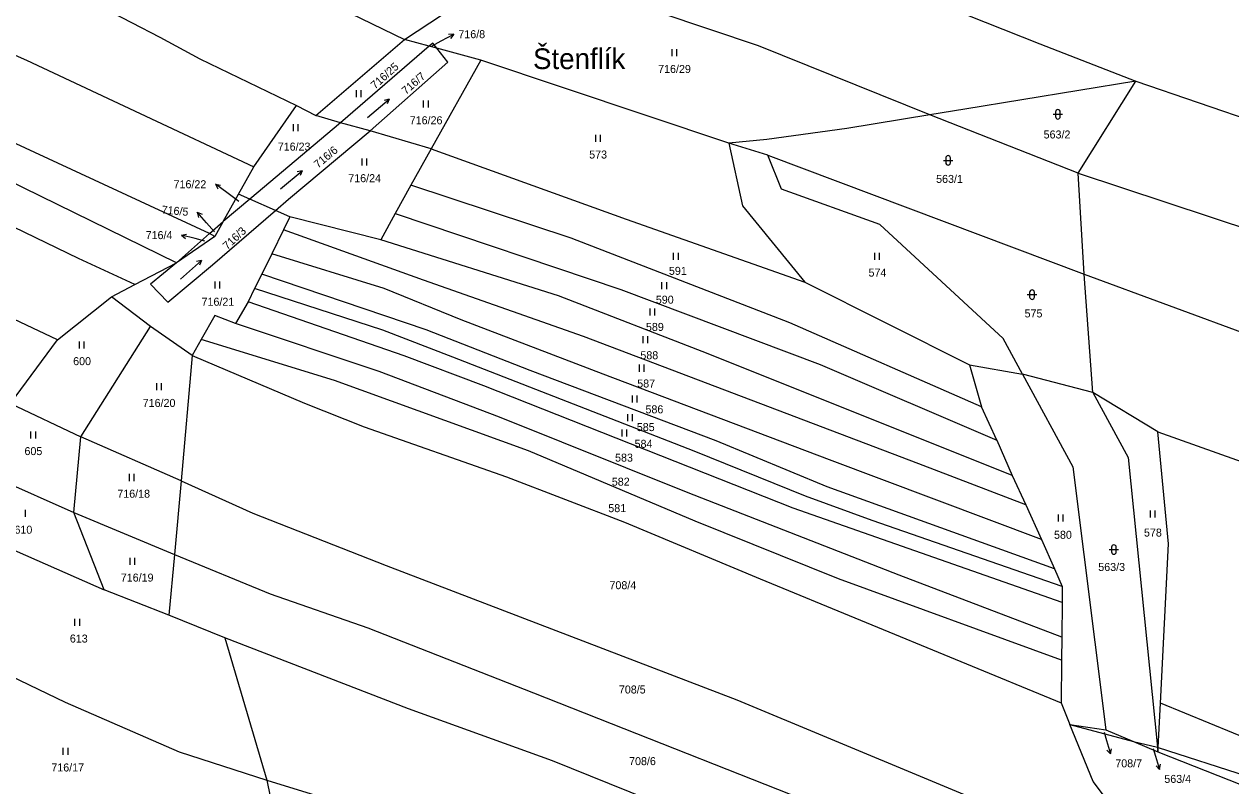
# Model space of a CAD drawing. Extents: x -751333 to -746055, y -1133395 to -1129777.
# Drawn here: x -748441 to -748184.6, y -1131157.3 to -1130995.4 of the extents above; entities that cross this region are included whole.
import ezdxf

# ---------------------------------------------------------------- set-up
doc = ezdxf.new("R2010")
doc.units = 0
for name, color, linetype in [('Hranice parcel', 7, 'Continuous'), ('Parcelní čísla', 7, 'Continuous'), ('Pop  PČ popisy', 7, 'Continuous'), ('Značky kultur', 7, 'Continuous')]:
    doc.layers.add(name, color=color, linetype=linetype)

msp = doc.modelspace()

# ---------------------------------------------------------------- linework, layer by layer
at = {"layer": 'Hranice parcel'}
for p, q in [((-748360.19, -1130998.63), (-748338.46, -1130984.21)), ((-748379, -1131014.81), (-748360.19, -1130998.63)), ((-748354.9, -1131000.06), (-748360.19, -1130998.63)), ((-748354.9, -1131000.06), (-748373.77, -1131016.38)), ((-748353.27, -1131000.5), (-748354.9, -1131000.06)), ((-748343.93, -1131003.03), (-748353.27, -1131000.5)), ((-748343.93, -1131003.03), (-748354.54, -1131021.9)), ((-748291.24, -1131020.69), (-748343.93, -1131003.03)), ((-748217.06, -1131027.07), (-748204.79, -1131007.48)), ((-748392.16, -1131025.73), (-748383.15, -1131012.7)), ((-748383.15, -1131012.7), (-748379, -1131014.81)), ((-748217.06, -1131027.07), (-748248.56, -1131014.62)), ((-748373.77, -1131016.38), (-748393.03, -1131032.57)), ((-748373.77, -1131016.38), (-748379, -1131014.81)), ((-748367.47, -1131018.07), (-748373.77, -1131016.38)), ((-748354.54, -1131021.9), (-748367.47, -1131018.07)), ((-748354.54, -1131021.9), (-748358.83, -1131029.64)), ((-748283.01, -1131023.21), (-748291.24, -1131020.69)), ((-748283.01, -1131023.21), (-748215.75, -1131048.5)), ((-748395.42, -1131031.51), (-748392.16, -1131025.73)), ((-748215.75, -1131048.5), (-748217.06, -1131027.07)), ((-748358.83, -1131029.64), (-748362.13, -1131035.6)), ((-748398.67, -1131037.3), (-748395.42, -1131031.51)), ((-748393.03, -1131032.57), (-748398.67, -1131037.3)), ((-748393.03, -1131032.57), (-748395.42, -1131031.51)), ((-748387.58, -1131034.98), (-748393.03, -1131032.57)), ((-748384.5, -1131036.34), (-748387.58, -1131034.98)), ((-748401.59, -1131039.86), (-748398.67, -1131037.3)), ((-748398.67, -1131037.3), (-748400.45, -1131040.5)), ((-748384.5, -1131036.34), (-748385.87, -1131039.12)), ((-748365.22, -1131041.21), (-748384.5, -1131036.34)), ((-748362.13, -1131035.6), (-748365.22, -1131041.21)), ((-748408.58, -1131046.09), (-748401.59, -1131039.86)), ((-748400.45, -1131040.5), (-748401.59, -1131039.86)), ((-748385.87, -1131039.12), (-748388.38, -1131044.22)), ((-748400.45, -1131040.5), (-748408.58, -1131046.09)), ((-748388.38, -1131044.22), (-748390.49, -1131048.5)), ((-748417.45, -1131050.74), (-748408.58, -1131046.09)), ((-748390.49, -1131048.5), (-748392.02, -1131051.59)), ((-748275.09, -1131050.22), (-748240.13, -1131067.81)), ((-748213.94, -1131073.65), (-748215.75, -1131048.5)), ((-748422.44, -1131053.36), (-748417.45, -1131050.74)), ((-748392.02, -1131051.59), (-748393.4, -1131054.38)), ((-748433.86, -1131062.5), (-748422.44, -1131053.36)), ((-748414.11, -1131059.62), (-748422.44, -1131053.36)), ((-748393.4, -1131054.38), (-748396.09, -1131058.99)), ((-748428.96, -1131083.09), (-748414.11, -1131059.62)), ((-748405.3, -1131065.79), (-748414.11, -1131059.62)), ((-748443.88, -1131076.03), (-748433.86, -1131062.5)), ((-748403.37, -1131062.41), (-748405.3, -1131065.79)), ((-748405.3, -1131065.79), (-748407.59, -1131092.49)), ((-748240.13, -1131067.81), (-748237.57, -1131076.74)), ((-748240.13, -1131067.81), (-748228.85, -1131069.78)), ((-748213.94, -1131073.65), (-748228.85, -1131069.78)), ((-748443.88, -1131076.03), (-748428.96, -1131083.09)), ((-748200.15, -1131082.03), (-748213.94, -1131073.65)), ((-748234.3, -1131083.82), (-748237.57, -1131076.74)), ((-748430.39, -1131099.21), (-748428.96, -1131083.09)), ((-748407.59, -1131092.49), (-748428.96, -1131083.09)), ((-748234.3, -1131083.82), (-748231.06, -1131091.34)), ((-748451.45, -1131089.82), (-748430.39, -1131099.21)), ((-748231.06, -1131091.34), (-748228.17, -1131097.58)), ((-748407.59, -1131092.49), (-748409.03, -1131108.09)), ((-748430.39, -1131099.21), (-748409.03, -1131108.09)), ((-748424, -1131115.63), (-748430.39, -1131099.21)), ((-748228.17, -1131097.58), (-748224.84, -1131104.96)), ((-748457.53, -1131100.91), (-748424, -1131115.63)), ((-748224.84, -1131104.96), (-748222.1, -1131111.15)), ((-748409.03, -1131108.09), (-748410.22, -1131121.04)), ((-748222.1, -1131111.15), (-748220.43, -1131114.9)), ((-748410.22, -1131121.04), (-748424, -1131115.63)), ((-748220.43, -1131114.9), (-748220.47, -1131118.31)), ((-748220.47, -1131118.31), (-748220.53, -1131125.72)), ((-748398.34, -1131125.81), (-748410.22, -1131121.04)), ((-748398.34, -1131125.81), (-748389.42, -1131156.09)), ((-748220.53, -1131125.72), (-748220.57, -1131130.55)), ((-748220.57, -1131130.55), (-748220.64, -1131139.62)), ((-748220.64, -1131139.62), (-748218.82, -1131144.23)), ((-748200.06, -1131149.14), (-748199.59, -1131139.75)), ((-748106.65, -1131177.93), (-748199.59, -1131139.75)), ((-748218.82, -1131144.23), (-748205.28, -1131147.89)), ((-748218.82, -1131144.23), (-748211.14, -1131145.42)), ((-748211.14, -1131145.42), (-748205.28, -1131147.89)), ((-748205.28, -1131147.89), (-748200.2, -1131149.11)), ((-748205.28, -1131147.89), (-748200.11, -1131150.07)), ((-748200.2, -1131149.11), (-748200.11, -1131150.07)), ((-748200.11, -1131150.07), (-748200.06, -1131149.14)), ((-748389.42, -1131156.09), (-748383.08, -1131187.24))]:
    msp.add_line(p, q, dxfattribs=at)
for points in [[(-748485.95, -1130936.62), (-748455.56, -1130954.14), (-748433.55, -1130964.26), (-748406.22, -1130976.23), (-748360.19, -1130998.63)], [(-748512.7, -1130944.65), (-748464.62, -1130973.2), (-748424.22, -1130991.94), (-748412.15, -1130998.16), (-748403.69, -1131002.73), (-748383.15, -1131012.7)], [(-748537.89, -1130953.74), (-748526.55, -1130964.01), (-748475.44, -1130987.44), (-748440.48, -1131003.02), (-748392.16, -1131025.73)], [(-748401.59, -1131039.86), (-748482.79, -1131002.25), (-748525.81, -1130981.98), (-748560.43, -1130965.34), (-748569.8, -1130959.62)], [(-748408.58, -1131046.09), (-748444.76, -1131028.43), (-748487.86, -1131009.7), (-748519.33, -1130996.05), (-748562.72, -1130976.46), (-748581.99, -1130964.07)], [(-748417.45, -1131050.74), (-748429.46, -1131045.22), (-748443.17, -1131038.57), (-748447.76, -1131036), (-748521.8, -1131003.51), (-748563.34, -1130984.99), (-748581.03, -1130975.42), (-748590.75, -1130967.27)], [(-748298.99, -1130970.22), (-748225.2, -1130999.57), (-748204.79, -1131007.48)], [(-748433.86, -1131062.5), (-748469.72, -1131045.54), (-748503.59, -1131029.98), (-748535.57, -1131015.06), (-748590.35, -1130992.22), (-748617.7, -1130976.74)], [(-748248.56, -1131014.62), (-748284.95, -1131000.02), (-748316.44, -1130989.36), (-748338.46, -1130984.21)], [(-748367.47, -1131018.07), (-748350.94, -1131003.46), (-748353.27, -1131000.5)], [(-748353.27, -1131000.5), (-748354.14, -1130999.4), (-748354.9, -1131000.06)], [(-748204.79, -1131007.48), (-748241.16, -1131013.45), (-748248.56, -1131014.62)], [(-748204.79, -1131007.48), (-748178.35, -1131016.55), (-748147.39, -1131029.12), (-748128.96, -1131036.36), (-748096.79, -1131049.01), (-748070.74, -1131060.67), (-748045.79, -1131075.87)], [(-748248.56, -1131014.62), (-748266.19, -1131017.56), (-748283.2, -1131019.93), (-748291.24, -1131020.69)], [(-748387.58, -1131034.98), (-748384.84, -1131032.61), (-748367.47, -1131018.07)], [(-748354.54, -1131021.9), (-748313.1, -1131036.82), (-748275.09, -1131050.22)], [(-748291.24, -1131020.69), (-748288.34, -1131033.98), (-748275.09, -1131050.22)], [(-748228.85, -1131069.78), (-748232.97, -1131062.2), (-748259.19, -1131037.98), (-748280.09, -1131030.45), (-748283.01, -1131023.21)], [(-748217.06, -1131027.07), (-748179.59, -1131039.45), (-748106.1, -1131070.73), (-748056.24, -1131094.99)], [(-748237.57, -1131076.74), (-748278.3, -1131058.9), (-748324.79, -1131040.88), (-748358.83, -1131029.64)], [(-748408.58, -1131046.09), (-748414.17, -1131050.66), (-748410.47, -1131054.51), (-748400.96, -1131046.55), (-748387.58, -1131034.98)], [(-748362.13, -1131035.6), (-748314.24, -1131051.8), (-748271.86, -1131067.7), (-748234.3, -1131083.82)], [(-748228.17, -1131097.58), (-748250.9, -1131088.82), (-748322.13, -1131061.79), (-748356.17, -1131049.78), (-748385.87, -1131039.12)], [(-748231.06, -1131091.34), (-748295.64, -1131065.48), (-748327.49, -1131053.12), (-748365.22, -1131041.21)], [(-748224.84, -1131104.96), (-748269.91, -1131088.03), (-748317.94, -1131069.78), (-748348.15, -1131058.2), (-748364.47, -1131051.6), (-748388.38, -1131044.22)], [(-748222.1, -1131111.15), (-748270.35, -1131093.73), (-748293.98, -1131083.95), (-748333.47, -1131069.02), (-748355.58, -1131060.36), (-748390.49, -1131048.5)], [(-748215.75, -1131048.5), (-748179.65, -1131061.85), (-748147.12, -1131075.88), (-748110.29, -1131091.1), (-748067.39, -1131114.45)], [(-748220.43, -1131114.9), (-748260.8, -1131100.91), (-748275, -1131095.72), (-748298.6, -1131086.14), (-748349.88, -1131066.18), (-748364.77, -1131060.43), (-748392.02, -1131051.59)], [(-748220.47, -1131118.31), (-748277.63, -1131098.3), (-748343.3, -1131072.28), (-748360.23, -1131065.88), (-748393.4, -1131054.38)], [(-748396.09, -1131058.99), (-748400.45, -1131057.32), (-748403.37, -1131062.41)], [(-748220.53, -1131125.72), (-748255.06, -1131112.5), (-748299.92, -1131094.99), (-748339.97, -1131078.96), (-748365.59, -1131069.23), (-748396.09, -1131058.99)], [(-748220.57, -1131130.55), (-748267.98, -1131113.3), (-748298.42, -1131101.04), (-748333.85, -1131086.07), (-748375.02, -1131071.11), (-748403.37, -1131062.41)], [(-748405.3, -1131065.79), (-748381.45, -1131075.94), (-748368.77, -1131080.97), (-748338.48, -1131091.58), (-748313.45, -1131101.22), (-748284.62, -1131113.32), (-748220.64, -1131139.62)], [(-748228.85, -1131069.78), (-748218.16, -1131089.46), (-748211.14, -1131145.42)], [(-748213.94, -1131073.65), (-748206.41, -1131087.48), (-748200.2, -1131149.11)], [(-748200.15, -1131082.03), (-748154.2, -1131098.38), (-748119.78, -1131111.85), (-748078.05, -1131132.75)], [(-748199.59, -1131139.75), (-748197.87, -1131105.84), (-748200.15, -1131082.03)], [(-748407.59, -1131092.49), (-748392.37, -1131099.36), (-748364.1, -1131110.45), (-748289.57, -1131139.04), (-748228.18, -1131164.59), (-748198.94, -1131176.25)], [(-748409.03, -1131108.09), (-748388.71, -1131116.46), (-748367.99, -1131123.74), (-748332.74, -1131137.52), (-748261.74, -1131165.6), (-748191.48, -1131193.81)], [(-748469.85, -1131122.34), (-748447.76, -1131132.08), (-748432.29, -1131139.48), (-748408.02, -1131150.06), (-748389.42, -1131156.09)], [(-748194.07, -1131207.17), (-748250.95, -1131183.36), (-748328.73, -1131151.99), (-748359.3, -1131140.91), (-748398.34, -1131125.81)], [(-748198.94, -1131176.25), (-748213.86, -1131156.39), (-748218.82, -1131144.23)], [(-748200.11, -1131150.07), (-748142.12, -1131172.94), (-748114.48, -1131184.54)], [(-748200.06, -1131149.14), (-748181.16, -1131155.26), (-748136.15, -1131172.02), (-748112.26, -1131184.92)], [(-748389.42, -1131156.09), (-748377.21, -1131159.87), (-748336.88, -1131177.2), (-748290.63, -1131196.06), (-748226.11, -1131222.02), (-748199.48, -1131232.89), (-748187.31, -1131238.43)]]:
    msp.add_lwpolyline(points, dxfattribs=at)
at = {"layer": 'Pop  PČ popisy'}
for p, q in [((-748354.3, -1130999.96), (-748352.37, -1130998.93)), ((-748352.37, -1130998.93), (-748349.72, -1130997.521)), ((-748349.72, -1130997.521), (-748350.84, -1130997.549)), ((-748349.72, -1130997.521), (-748350.369, -1130998.433)), ((-748397.94, -1131031.2), (-748400.337, -1131029.394)), ((-748400.337, -1131029.394), (-748399.236, -1131029.597)), ((-748400.337, -1131029.394), (-748399.838, -1131030.397)), ((-748395.38, -1131033.11), (-748397.94, -1131031.2)), ((-748402.22, -1131037.64), (-748404.189, -1131035.375)), ((-748404.189, -1131035.375), (-748403.154, -1131035.802)), ((-748404.189, -1131035.375), (-748403.91, -1131036.459)), ((-748400.57, -1131039.56), (-748402.22, -1131037.64)), ((-748407.572, -1131040.234), (-748406.479, -1131039.99)), ((-748404.66, -1131040.96), (-748407.572, -1131040.234)), ((-748407.572, -1131040.234), (-748406.721, -1131040.962)), ((-748402.56, -1131041.48), (-748404.66, -1131040.96)), ((-748211.51, -1131145.87), (-748211, -1131147.64)), ((-748211, -1131147.64), (-748210.173, -1131150.525)), ((-748210.173, -1131150.525), (-748210.93, -1131149.7)), ((-748210.173, -1131150.525), (-748209.968, -1131149.424)), ((-748201.1, -1131149.36), (-748200.62, -1131150.96)), ((-748200.62, -1131150.96), (-748199.743, -1131153.83)), ((-748199.743, -1131153.83), (-748200.514, -1131153.019)), ((-748199.743, -1131153.83), (-748199.557, -1131152.726))]:
    msp.add_line(p, q, dxfattribs=at)
at = {"layer": 'Značky kultur'}
for p, q in [((-748303.341, -1131002.2), (-748303.341, -1131000.7)), ((-748302.34, -1131002.2), (-748302.34, -1131000.7)), ((-748370.361, -1131010.9), (-748370.361, -1131009.4)), ((-748369.36, -1131010.9), (-748369.36, -1131009.4)), ((-748368.019, -1131015.194), (-748363.423, -1131011.337)), ((-748363.423, -1131011.337), (-748364.494, -1131011.581)), ((-748363.423, -1131011.337), (-748363.849, -1131012.349)), ((-748356.111, -1131013.11), (-748356.111, -1131011.61)), ((-748355.11, -1131013.11), (-748355.11, -1131011.61)), ((-748222.371, -1131014.541), (-748220.369, -1131014.541)), ((-748221.871, -1131014.041), (-748221.871, -1131015.042)), ((-748220.869, -1131015.042), (-748220.869, -1131014.041)), ((-748383.771, -1131018.16), (-748383.771, -1131016.66)), ((-748382.77, -1131018.16), (-748382.77, -1131016.66)), ((-748319.541, -1131020.39), (-748319.541, -1131018.89)), ((-748318.54, -1131020.39), (-748318.54, -1131018.89)), ((-748369.171, -1131025.42), (-748369.171, -1131023.92)), ((-748368.17, -1131025.42), (-748368.17, -1131023.92)), ((-748245.691, -1131024.331), (-748243.689, -1131024.331)), ((-748245.191, -1131023.831), (-748245.191, -1131024.832)), ((-748244.189, -1131024.832), (-748244.189, -1131023.831)), ((-748386.509, -1131030.384), (-748381.913, -1131026.527)), ((-748381.913, -1131026.527), (-748382.984, -1131026.771)), ((-748381.913, -1131026.527), (-748382.339, -1131027.539)), ((-748302.991, -1131045.5), (-748302.991, -1131044)), ((-748301.99, -1131045.5), (-748301.99, -1131044)), ((-748260.271, -1131045.49), (-748260.271, -1131043.99)), ((-748259.27, -1131045.49), (-748259.27, -1131043.99)), ((-748407.781, -1131049.602), (-748403.322, -1131045.588)), ((-748403.322, -1131045.588), (-748404.384, -1131045.869)), ((-748403.322, -1131045.588), (-748403.713, -1131046.614)), ((-748400.401, -1131051.56), (-748400.401, -1131050.06)), ((-748399.4, -1131051.56), (-748399.4, -1131050.06)), ((-748305.471, -1131051.74), (-748305.471, -1131050.24)), ((-748304.47, -1131051.74), (-748304.47, -1131050.24)), ((-748227.861, -1131052.881), (-748225.859, -1131052.881)), ((-748227.361, -1131052.381), (-748227.361, -1131053.382)), ((-748226.359, -1131053.382), (-748226.359, -1131052.381)), ((-748307.991, -1131057.29), (-748307.991, -1131055.79)), ((-748306.99, -1131057.29), (-748306.99, -1131055.79)), ((-748429.211, -1131064.32), (-748429.211, -1131062.82)), ((-748428.21, -1131064.32), (-748428.21, -1131062.82)), ((-748309.471, -1131063.2), (-748309.471, -1131061.7)), ((-748308.47, -1131063.2), (-748308.47, -1131061.7)), ((-748310.281, -1131069.26), (-748310.281, -1131067.76)), ((-748309.28, -1131069.26), (-748309.28, -1131067.76)), ((-748412.821, -1131073.2), (-748412.821, -1131071.7)), ((-748411.82, -1131073.2), (-748411.82, -1131071.7)), ((-748311.711, -1131075.79), (-748311.711, -1131074.29)), ((-748310.71, -1131075.79), (-748310.71, -1131074.29)), ((-748312.701, -1131079.81), (-748312.701, -1131078.31)), ((-748311.7, -1131079.81), (-748311.7, -1131078.31)), ((-748439.531, -1131083.44), (-748439.531, -1131081.94)), ((-748438.53, -1131083.44), (-748438.53, -1131081.94)), ((-748313.961, -1131083.06), (-748313.961, -1131081.56)), ((-748312.96, -1131083.06), (-748312.96, -1131081.56)), ((-748418.591, -1131092.5), (-748418.591, -1131091)), ((-748417.59, -1131092.5), (-748417.59, -1131091)), ((-748440.72, -1131100.14), (-748440.72, -1131098.64)), ((-748201.671, -1131100.28), (-748201.671, -1131098.78)), ((-748200.67, -1131100.28), (-748200.67, -1131098.78)), ((-748221.221, -1131101.14), (-748221.221, -1131099.64)), ((-748220.22, -1131101.14), (-748220.22, -1131099.64)), ((-748209.971, -1131106.571), (-748209.971, -1131107.572)), ((-748208.969, -1131107.572), (-748208.969, -1131106.571)), ((-748418.451, -1131110.34), (-748418.451, -1131108.84)), ((-748417.45, -1131110.34), (-748417.45, -1131108.84)), ((-748210.471, -1131107.071), (-748208.469, -1131107.071)), ((-748430.181, -1131123.29), (-748430.181, -1131121.79)), ((-748429.18, -1131123.29), (-748429.18, -1131121.79)), ((-748432.661, -1131150.7), (-748432.661, -1131149.2)), ((-748431.66, -1131150.7), (-748431.66, -1131149.2))]:
    msp.add_line(p, q, dxfattribs=at)
for centre, start, end in [((-748221.37, -1131014.041), 0, 180), ((-748221.37, -1131015.041), 180, 359.98789), ((-748244.69, -1131023.831), 0, 180), ((-748244.69, -1131024.831), 180, 359.98789), ((-748226.86, -1131052.381), 0, 180), ((-748226.86, -1131053.381), 180, 359.98789), ((-748209.47, -1131106.571), 0, 180), ((-748209.47, -1131107.571), 180, 359.98789)]:
    msp.add_arc(centre, 0.5, start, end, dxfattribs=at)

# ---------------------------------------------------------------- texts
at = {"layer": 'Parcelní čísla'}
for s, p in [('716/8', (-748348.73, -1130998.36)), ('716/29', (-748306.29, -1131005.75)), ('716/26', (-748359.06, -1131016.66)), ('563/2', (-748224.39, -1131019.68)), ('716/23', (-748387.1, -1131022.26)), ('573', (-748320.94, -1131023.94)), ('716/24', (-748372.12, -1131028.97)), ('563/1', (-748247.23, -1131029.13)), ('716/22', (-748409.235, -1131030.26)), ('716/4', (-748415.167, -1131041.08)), ('591', (-748304, -1131048.67)), ('574', (-748261.59, -1131049.04)), ('590', (-748306.78, -1131054.8)), ('716/21', (-748403.29, -1131055.24)), ('575', (-748228.44, -1131057.72)), ('589', (-748308.88, -1131060.59)), ('588', (-748310.06, -1131066.61)), ('600', (-748430.57, -1131067.87)), ('587', (-748310.73, -1131072.62)), ('716/20', (-748415.79, -1131076.75)), ('586', (-748308.98, -1131078.11)), ('585', (-748310.82, -1131081.89)), ('584', (-748311.29, -1131085.44)), ('605', (-748440.91, -1131086.99)), ('583', (-748315.44, -1131088.38)), ('582', (-748316.13, -1131093.49)), ('716/18', (-748421.19, -1131096.05)), ('581', (-748316.87, -1131099.12)), ('610', (-748443.04, -1131103.7)), ('580', (-748222.18, -1131104.78)), ('578', (-748203.07, -1131104.31)), ('563/3', (-748212.78, -1131111.62)), ('716/19', (-748420.45, -1131113.88)), ('708/4', (-748316.63, -1131115.5)), ('613', (-748431.27, -1131126.84)), ('708/5', (-748314.63, -1131137.67)), ('716/17', (-748435.2, -1131154.25)), ('708/6', (-748312.46, -1131152.9)), ('708/7', (-748209.16, -1131153.368)), ('563/4', (-748198.75, -1131156.678))]:
    msp.add_text(s, height=1.7, dxfattribs=at).set_placement(p)
for s, rotation, p in [('716/25', 42, (-748366.411, -1131009.301)), ('716/7', 41, (-748359.862, -1131010.451)), ('716/6', 40, (-748378.533, -1131026.101)), ('716/5', 355, (-748411.826, -1131035.641)), ('716/3', 43, (-748397.81, -1131043.431))]:
    msp.add_text(s, height=1.7, rotation=rotation, dxfattribs=at).set_placement(p)
at = {"layer": 'Pop  PČ popisy'}
msp.add_text('Štenflík', height=4.4, dxfattribs=at).set_placement((-748332.87, -1131004.93))

doc.saveas('drawing.dxf')
